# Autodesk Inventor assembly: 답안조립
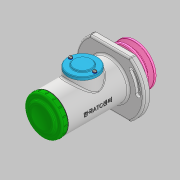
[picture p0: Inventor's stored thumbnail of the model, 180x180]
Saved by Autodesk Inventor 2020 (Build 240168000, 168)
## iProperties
Created: 2022-05
Part Number: 답안조립
Document SubType Name: Assembly
Designer: User
Author: User
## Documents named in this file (22)
- C:\Users\User\Desktop\720506V1036\답안조립.iam
- C:\Users\User\Desktop\720506V1036\본체.ipt
- C:\Users\User\Desktop\720506V1036\볼트 M4 x 10.ipt
- C:\Users\User\Desktop\720506V1036\부시1.ipt
- C:\Users\User\Desktop\720506V1036\부시2.ipt
- C:\Users\User\Desktop\720506V1036\사이드 커버.ipt
- 사이드 커버.ipt
- C:\Users\User\Desktop\720506V1036\십자볼트 M3 x 10.ipt
- C:\Users\User\Desktop\720506V1036\오일 실 15 x 30 x 7.ipt
- C:\Users\User\Desktop\720506V1036\와셔 3 x 6.ipt
- C:\Users\User\Desktop\720506V1036\와셔 4 x 16.ipt
- C:\Users\User\Desktop\720506V1036\와셔 10 x 21.ipt
- C:\Users\User\Desktop\720506V1036\축.ipt
- C:\Users\User\Desktop\720506V1036\키 4 x 4.ipt
- C:\Users\User\Desktop\720506V1036\탑 커버.ipt
- C:\Users\User\Desktop\720506V1036\V-벨트풀리.ipt
- C:\Users\User\Desktop\720506V1036\개스킷.ipt
- C:\Users\User\Desktop\720506V1036\너트 M10.ipt
- C:\Users\User\Desktop\720506V1036\멈춤나사 M3.ipt
- C:\Users\User\Desktop\720506V1036\멈춤링 15 x 1.ipt
- C:\Users\User\Desktop\720506V1036\멈춤링 35 x 1.6.ipt
- C:\Users\User\Desktop\720506V1036\베어링 6202.ipt
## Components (3 placed, 3 different names)
1. V-벨트풀리:1
2. 개스킷:1
3. ISO 4017 M4 x 10:1 — 각도:4, 각도:5
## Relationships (2: Angle 2)
- 각도:4 [Angle]: ISO 4017 M4 x 10:1
- 각도:5 [Angle]: ISO 4017 M4 x 10:1
